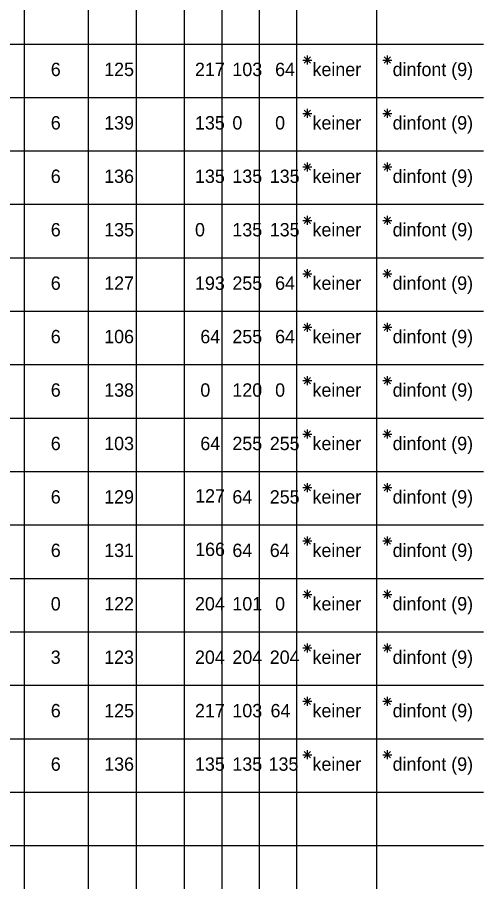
# Model space of a CAD drawing. Extents: x -29 to 48, y -113 to 16.
# Drawn here: x 23.27 to 31.89, y -63.68 to -47.5 of the extents above; entities that cross this region are included whole.
import ezdxf

# ---------------------------------------------------------------- set-up
doc = ezdxf.new("R2010")
doc.units = 0
doc.layers.add('Default', color=7, linetype='Continuous')

msp = doc.modelspace()

# ---------------------------------------------------------------- linework, layer by layer
at = {"layer": 'Default'}
for p, q in [((23.4, -0.7), (23.4, -89)), ((24.6, -0.7), (24.6, -89)), ((25.5, -0.7), (25.5, -89)), ((26.4, -0.7), (26.4, -89)), ((28.5, -0.7), (28.5, -96)), ((30, -0.7), (30, -96)), ((27.1, -1.5), (27.1, -89)), ((27.8, -1.5), (27.8, -89)), ((0, -48), (32, -48)), ((28.616, -48.3), (28.784, -48.3)), ((28.641, -48.241), (28.759, -48.359)), ((28.759, -48.241), (28.641, -48.359)), ((28.7, -48.216), (28.7, -48.384)), ((30.116, -48.3), (30.284, -48.3)), ((30.141, -48.241), (30.259, -48.359)), ((30.259, -48.241), (30.141, -48.359)), ((30.2, -48.216), (30.2, -48.384)), ((0, -49), (32, -49)), ((28.616, -49.3), (28.784, -49.3)), ((28.641, -49.241), (28.759, -49.359)), ((28.759, -49.241), (28.641, -49.359)), ((28.7, -49.216), (28.7, -49.384)), ((30.116, -49.3), (30.284, -49.3)), ((30.141, -49.241), (30.259, -49.359)), ((30.259, -49.241), (30.141, -49.359)), ((30.2, -49.216), (30.2, -49.384)), ((0, -50), (32, -50)), ((28.616, -50.3), (28.784, -50.3)), ((28.641, -50.241), (28.759, -50.359)), ((28.759, -50.241), (28.641, -50.359)), ((28.7, -50.216), (28.7, -50.384)), ((30.116, -50.3), (30.284, -50.3)), ((30.141, -50.241), (30.259, -50.359)), ((30.259, -50.241), (30.141, -50.359)), ((30.2, -50.216), (30.2, -50.384)), ((0, -51), (32, -51)), ((28.641, -51.241), (28.759, -51.359)), ((28.759, -51.241), (28.641, -51.359)), ((28.7, -51.216), (28.7, -51.384)), ((30.141, -51.241), (30.259, -51.359)), ((30.259, -51.241), (30.141, -51.359)), ((30.2, -51.216), (30.2, -51.384)), ((28.616, -51.3), (28.784, -51.3)), ((30.116, -51.3), (30.284, -51.3)), ((0, -52), (32, -52)), ((28.641, -52.241), (28.759, -52.359)), ((28.759, -52.241), (28.641, -52.359)), ((28.7, -52.216), (28.7, -52.384)), ((30.141, -52.241), (30.259, -52.359)), ((30.259, -52.241), (30.141, -52.359)), ((30.2, -52.216), (30.2, -52.384)), ((28.616, -52.3), (28.784, -52.3)), ((30.116, -52.3), (30.284, -52.3)), ((0, -53), (32, -53)), ((28.7, -53.216), (28.7, -53.384)), ((30.2, -53.216), (30.2, -53.384)), ((28.616, -53.3), (28.784, -53.3)), ((28.641, -53.241), (28.759, -53.359)), ((28.759, -53.241), (28.641, -53.359)), ((30.116, -53.3), (30.284, -53.3)), ((30.141, -53.241), (30.259, -53.359)), ((30.259, -53.241), (30.141, -53.359)), ((0, -54), (32, -54)), ((28.616, -54.3), (28.784, -54.3)), ((28.641, -54.241), (28.759, -54.359)), ((28.759, -54.241), (28.641, -54.359)), ((28.7, -54.216), (28.7, -54.384)), ((30.116, -54.3), (30.284, -54.3)), ((30.141, -54.241), (30.259, -54.359)), ((30.259, -54.241), (30.141, -54.359)), ((30.2, -54.216), (30.2, -54.384)), ((0, -55), (32, -55)), ((28.616, -55.3), (28.784, -55.3)), ((28.641, -55.241), (28.759, -55.359)), ((28.759, -55.241), (28.641, -55.359)), ((28.7, -55.216), (28.7, -55.384)), ((30.116, -55.3), (30.284, -55.3)), ((30.141, -55.241), (30.259, -55.359)), ((30.259, -55.241), (30.141, -55.359)), ((30.2, -55.216), (30.2, -55.384)), ((0, -56), (32, -56)), ((28.641, -56.241), (28.759, -56.359)), ((28.759, -56.241), (28.641, -56.359)), ((28.7, -56.216), (28.7, -56.384)), ((30.141, -56.241), (30.259, -56.359)), ((30.259, -56.241), (30.141, -56.359)), ((30.2, -56.216), (30.2, -56.384)), ((28.616, -56.3), (28.784, -56.3)), ((30.116, -56.3), (30.284, -56.3)), ((0, -57), (32, -57)), ((28.641, -57.241), (28.759, -57.359)), ((28.759, -57.241), (28.641, -57.359)), ((28.7, -57.216), (28.7, -57.384)), ((30.141, -57.241), (30.259, -57.359)), ((30.259, -57.241), (30.141, -57.359)), ((30.2, -57.216), (30.2, -57.384)), ((28.616, -57.3), (28.784, -57.3)), ((30.116, -57.3), (30.284, -57.3)), ((0, -58), (32, -58)), ((28.7, -58.216), (28.7, -58.384)), ((30.2, -58.216), (30.2, -58.384)), ((28.616, -58.3), (28.784, -58.3)), ((28.641, -58.241), (28.759, -58.359)), ((28.759, -58.241), (28.641, -58.359)), ((30.116, -58.3), (30.284, -58.3)), ((30.141, -58.241), (30.259, -58.359)), ((30.259, -58.241), (30.141, -58.359)), ((0, -59), (32, -59)), ((28.616, -59.3), (28.784, -59.3)), ((28.641, -59.241), (28.759, -59.359)), ((28.759, -59.241), (28.641, -59.359)), ((28.7, -59.216), (28.7, -59.384)), ((30.116, -59.3), (30.284, -59.3)), ((30.141, -59.241), (30.259, -59.359)), ((30.259, -59.241), (30.141, -59.359)), ((30.2, -59.216), (30.2, -59.384)), ((0, -60), (32, -60)), ((28.616, -60.3), (28.784, -60.3)), ((28.641, -60.241), (28.759, -60.359)), ((28.759, -60.241), (28.641, -60.359)), ((28.7, -60.216), (28.7, -60.384)), ((30.116, -60.3), (30.284, -60.3)), ((30.141, -60.241), (30.259, -60.359)), ((30.259, -60.241), (30.141, -60.359)), ((30.2, -60.216), (30.2, -60.384)), ((0, -61), (32, -61)), ((28.616, -61.3), (28.784, -61.3)), ((28.641, -61.241), (28.759, -61.359)), ((28.759, -61.241), (28.641, -61.359)), ((28.7, -61.216), (28.7, -61.384)), ((30.116, -61.3), (30.284, -61.3)), ((30.141, -61.241), (30.259, -61.359)), ((30.259, -61.241), (30.141, -61.359)), ((30.2, -61.216), (30.2, -61.384)), ((0, -62), (32, -62)), ((0, -63), (32, -63))]:
    msp.add_line(p, q, dxfattribs=at)

# ---------------------------------------------------------------- texts
for s, p in [('6', (23.9, -48.6)), ('125', (24.9, -48.6)), ('217', (26.6, -48.6)), ('103', (27.3, -48.6)), ('64', (28.1, -48.6)), ('keiner', (28.8, -48.6)), ('dinfont (9)', (30.3, -48.6)), ('keiner', (28.8, -49.6)), ('dinfont (9)', (30.3, -49.6)), ('6', (23.9, -49.6)), ('139', (24.9, -49.6)), ('135', (26.6, -49.6)), ('0', (27.3, -49.6)), ('0', (28.1, -49.6)), ('6', (23.9, -50.6)), ('136', (24.9, -50.6)), ('135', (26.6, -50.6)), ('135', (27.3, -50.6)), ('135', (28, -50.6)), ('keiner', (28.8, -50.6)), ('dinfont (9)', (30.3, -50.6)), ('6', (23.9, -51.6)), ('135', (24.9, -51.6)), ('0', (26.6, -51.6)), ('135', (27.3, -51.6)), ('135', (28, -51.6)), ('keiner', (28.8, -51.6)), ('dinfont (9)', (30.3, -51.6)), ('6', (23.9, -52.6)), ('127', (24.9, -52.6)), ('193', (26.6, -52.6)), ('255', (27.3, -52.6)), ('64', (28.1, -52.6)), ('keiner', (28.8, -52.6)), ('dinfont (9)', (30.3, -52.6)), ('6', (23.9, -53.6)), ('106', (24.9, -53.6)), ('64', (26.7, -53.6)), ('255', (27.3, -53.6)), ('64', (28.1, -53.6)), ('keiner', (28.8, -53.6)), ('dinfont (9)', (30.3, -53.6)), ('6', (23.9, -54.6)), ('138', (24.9, -54.6)), ('0', (26.7, -54.6)), ('120', (27.3, -54.6)), ('0', (28.1, -54.6)), ('keiner', (28.8, -54.6)), ('dinfont (9)', (30.3, -54.6)), ('6', (23.9, -55.6)), ('103', (24.9, -55.6)), ('64', (26.7, -55.6)), ('255', (27.3, -55.6)), ('255', (28, -55.6)), ('keiner', (28.8, -55.6)), ('dinfont (9)', (30.3, -55.6)), ('6', (23.9, -56.6)), ('129', (24.9, -56.6)), ('127', (26.603, -56.581)), ('64', (27.3, -56.6)), ('255', (28, -56.6)), ('keiner', (28.8, -56.6)), ('dinfont (9)', (30.3, -56.6)), ('6', (23.9, -57.6)), ('131', (24.9, -57.6)), ('166', (26.603, -57.581)), ('64', (27.3, -57.6)), ('64', (28, -57.6)), ('keiner', (28.8, -57.6)), ('dinfont (9)', (30.3, -57.6)), ('0', (23.9, -58.6)), ('122', (24.9, -58.6)), ('204', (26.6, -58.6)), ('101', (27.3, -58.6)), ('0', (28.1, -58.6)), ('keiner', (28.8, -58.6)), ('dinfont (9)', (30.3, -58.6)), ('3', (23.9, -59.6)), ('123', (24.9, -59.6)), ('204', (26.6, -59.6)), ('204', (27.3, -59.6)), ('204', (28, -59.6)), ('keiner', (28.8, -59.6)), ('dinfont (9)', (30.3, -59.6)), ('keiner', (28.8, -60.6)), ('dinfont (9)', (30.3, -60.6)), ('6', (23.9, -60.6)), ('125', (24.9, -60.6)), ('217', (26.6, -60.6)), ('103', (27.3, -60.6)), ('64', (28.014, -60.6)), ('6', (23.9, -61.6)), ('136', (24.9, -61.6)), ('135', (26.6, -61.6)), ('135', (27.3, -61.6)), ('135', (27.977, -61.6)), ('keiner', (28.8, -61.6)), ('dinfont (9)', (30.3, -61.6))]:
    msp.add_text(s, height=0.25, dxfattribs=at).set_placement(p)

doc.saveas('drawing.dxf')
